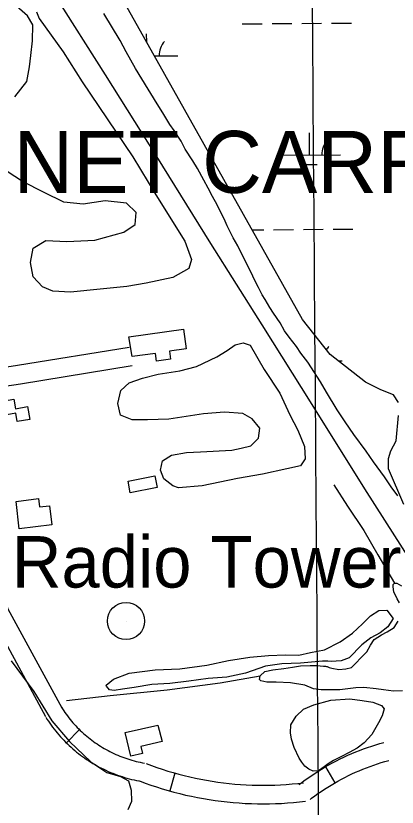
# Model space of a CAD drawing. Extents: x 3540316 to 3578335, y 553172 to 578787.
# Drawn here: x 3554547 to 3555162, y 562806 to 564084 of the extents above; entities that cross this region are included whole.
import ezdxf

# ---------------------------------------------------------------- set-up
doc = ezdxf.new("R2010")
doc.units = 0
for name, color, linetype in [('V-BLDG-OTLN', 7, 'Continuous'), ('V-GRID-MAJR', 7, 'Continuous'), ('V-RAIL-TRAK', 7, 'Continuous'), ('V-RIVR-IDEN', 7, 'Continuous'), ('V-ROAD-CNTR', 7, 'Continuous'), ('V-SITE-VEGE', 7, 'Continuous'), ('V-TOPO-SHOR', 7, 'Continuous'), ('V-TOPO-TOWR', 7, 'Continuous'), ('V-TOPO-TOWR-IDEN', 7, 'Continuous'), ('V-WETL-SWMP', 7, 'Continuous')]:
    doc.layers.add(name, color=color, linetype=linetype)

msp = doc.modelspace()

# ---------------------------------------------------------------- linework, layer by layer
at = {"layer": 'V-BLDG-OTLN'}
for points in [[(3554729.205, 563565.561), (3554817.251, 563577.914), (3554821.701, 563546.1950000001), (3554794.52, 563542.382), (3554796.345, 563529.371), (3554773.843, 563526.227), (3554772.0640000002, 563538.902), (3554734.4620000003, 563533.626)], [(3554503.2, 563457.83), (3554543.451, 563464.742), (3554546.0670000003, 563449.503), (3554565.463, 563452.833), (3554569.051, 563432.121), (3554548.9220000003, 563428.634), (3554546.538, 563442.2980000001), (3554526.035, 563438.7220000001), (3554526.764, 563434.54), (3554507.31, 563431.149)], [(3554727.659, 563332.802), (3554771.1890000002, 563341.252), (3554774.9020000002, 563322.117), (3554731.3170000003, 563313.657)], [(3554547.029, 563299.821), (3554583.363, 563304.304), (3554585.018, 563290.881), (3554600.953, 563292.8470000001), (3554604.762, 563261.969), (3554552.19, 563255.485)], [(3554782.986, 562912.378), (3554748.286, 562904.358), (3554750.883, 562893.125), (3554732.007, 562888.769), (3554723.247, 562926.689), (3554775.582, 562938.779)]]:
    msp.add_lwpolyline(points, close=True, dxfattribs=at)
at = {"layer": 'V-GRID-MAJR'}
msp.add_spline([(3555066.6580000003, 558654.5920000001), (3555020.84, 564712.414), (3554974.9990000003, 570773.3200000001), (3554929.157, 576834.2440000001), (3554929.134, 576837.311)], degree=3, dxfattribs=at)
at = {"layer": 'V-RAIL-TRAK'}
msp.add_lwpolyline([(3553552.8850000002, 565794.377), (3553643.91, 565648.182), (3553727.27, 565516.779), (3553808.107, 565388.318), (3553891.9760000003, 565255.927), (3553971.3000000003, 565128.934), (3554066.859, 564978.337), (3554158.892, 564831.1630000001), (3554249.887, 564686.956), (3554335.811, 564550.127), (3554428.325, 564403.955), (3554518.81, 564260.734), (3554609.3030000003, 564117.0160000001), (3554690.633, 563988.561), (3554773.503, 563856.653), (3554860.967, 563716.367), (3554943.8310000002, 563584.955), (3555024.168, 563456.488), (3555109.586, 563320.147), (3555202.59, 563174.479)], dxfattribs=at)
at = {"layer": 'V-ROAD-CNTR'}
for p, q in [((3554649.1916632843, 562931.471110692), (3554628.2667051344, 562909.9741536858)), ((3555046.55286856, 562871.510230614), (3555061.4498387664, 562845.4702826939)), ((3554803.11835543, 562861.2882510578), (3554795.0663715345, 562832.389308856))]:
    msp.add_line(p, q, dxfattribs=at)
for points in [[(3554374.667566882, 563496.3316520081), (3554427.0817231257, 563501.1916746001), (3554549.3744312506, 563519.5662000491), (3554729.293821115, 563549.1305035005)], [(3554379.316310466, 563466.634011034), (3554430.6982768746, 563471.3983253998), (3554554.0355687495, 563489.9297999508), (3554734.158178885, 563519.5274964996)], [(3554507.7519461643, 563196.724580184), (3554533.7138942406, 563126.6897202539), (3554620.676720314, 562966.791040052)], [(3554510.959939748, 563105.7367621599), (3554594.322773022, 562952.4570687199)], [(3554620.1637213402, 562967.6630383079), (3554621.991717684, 562964.7830440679), (3554623.914713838, 562961.89204985), (3554625.885709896, 562959.028055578), (3554627.902705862, 562956.1990612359), (3554629.949701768, 562953.4240667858), (3554632.081697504, 562950.6740722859), (3554634.2366931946, 562947.94207775), (3554636.4476887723, 562945.276083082), (3554638.7136842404, 562942.60708842), (3554640.97367972, 562940.058093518), (3554643.3426749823, 562937.4880986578), (3554645.7576701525, 562934.9351037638), (3554648.15366536, 562932.48210867), (3554650.625660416, 562930.0741134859), (3554653.1836553, 562927.6401183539), (3554655.7206502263, 562925.3091230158), (3554658.306645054, 562923.0291275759), (3554660.9466397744, 562920.7821320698), (3554663.6636343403, 562918.5441365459), (3554666.3486289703, 562916.3881408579), (3554669.086623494, 562914.304145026), (3554671.882617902, 562912.2311491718), (3554674.726612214, 562910.2111532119), (3554677.584606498, 562908.236157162), (3554680.4696007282, 562906.3391609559), (3554683.4165948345, 562904.4571647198), (3554686.347588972, 562902.6571683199), (3554689.33858299, 562900.90217183), (3554692.3755769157, 562899.1871752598), (3554695.424570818, 562897.5221785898), (3554698.4875646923, 562895.935181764), (3554701.5945584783, 562894.38218487), (3554704.72855221, 562892.9011878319), (3554707.9245458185, 562891.438190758), (3554711.081539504, 562890.0571935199), (3554714.252533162, 562888.743196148), (3554717.492526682, 562887.4841986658), (3554720.765520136, 562886.255201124), (3554724.0515135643, 562885.090203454), (3554727.335506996, 562883.9872056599), (3554730.5975004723, 562882.954207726), (3554733.9454937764, 562881.9812096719), (3554737.320487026, 562881.0382115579), (3554740.6354803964, 562880.175213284), (3554744.0314736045, 562879.374214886), (3554747.45846675, 562878.6082164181), (3554750.810460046, 562877.918217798), (3554754.320453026, 562877.2792190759)], [(3554594.835771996, 562951.585070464), (3554596.835767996, 562948.4350767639), (3554599.066763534, 562945.0800834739), (3554601.31375904, 562941.8160900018), (3554603.6147544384, 562938.5870964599), (3554606.019749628, 562935.3261029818), (3554608.4517447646, 562932.1901092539), (3554610.9107398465, 562929.0741154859), (3554613.4637347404, 562925.9941216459), (3554616.051729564, 562922.945127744), (3554618.719724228, 562919.9361337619), (3554621.416718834, 562917.0121396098), (3554624.1277134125, 562914.1451453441), (3554626.9557077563, 562911.250151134), (3554629.8197020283, 562908.4621567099), (3554632.6916962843, 562905.7281621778), (3554635.6486903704, 562903.0111676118), (3554638.6626843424, 562900.3531729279), (3554641.686678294, 562897.7801780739), (3554644.7336722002, 562895.2701830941), (3554647.86866593, 562892.7521881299), (3554651.066659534, 562890.318192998), (3554654.260653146, 562887.949197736), (3554657.514646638, 562885.6392023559), (3554660.8126400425, 562883.360206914), (3554664.15363336, 562881.1632113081), (3554667.4906266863, 562879.0312155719), (3554670.907619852, 562876.9332197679), (3554674.370612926, 562874.90222383), (3554677.8096060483, 562872.959227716), (3554681.336598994, 562871.034231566), (3554684.879591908, 562869.1992352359), (3554688.476584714, 562867.400238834), (3554692.0765775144, 562865.6992422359), (3554695.670570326, 562864.0542455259), (3554699.327563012, 562862.455248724), (3554703.0765555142, 562860.901251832), (3554706.786548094, 562859.460254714), (3554710.4775407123, 562858.0732574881), (3554714.261533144, 562856.73226017), (3554718.0295256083, 562855.465262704), (3554721.8815179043, 562854.246265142), (3554725.7215102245, 562853.1292673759), (3554729.506502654, 562852.07226949), (3554733.415494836, 562851.055271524), (3554737.315487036, 562850.136273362), (3554741.156479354, 562849.2762750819), (3554745.096471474, 562848.464276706), (3554748.94846377, 562847.7632781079)], [(3555003.3649549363, 562842.578288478), (3555005.7949500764, 562844.44228475), (3555011.2839390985, 562848.5382765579), (3555016.894927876, 562852.553268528), (3555022.5049166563, 562856.431260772), (3555028.2459051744, 562860.2772530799), (3555034.026893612, 562863.9702456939), (3555039.904881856, 562867.6082384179), (3555045.813870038, 562871.0872314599), (3555051.7458581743, 562874.4812246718), (3555057.7558461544, 562877.78721806), (3555063.90783385, 562881.0172115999), (3555070.0468215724, 562884.068205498), (3555076.1848092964, 562887.033199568), (3555082.461796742, 562889.9191937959), (3555088.724784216, 562892.678188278), (3555095.106771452, 562895.3551829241), (3555101.518758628, 562897.868177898), (3555107.8737459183, 562900.28217307), (3555114.384732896, 562902.6231683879), (3555120.92771981, 562904.806164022), (3555127.4127068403, 562906.890159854), (3555134.013693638, 562908.8861558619), (3555140.5676805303, 562910.704152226)], [(3554756.8754479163, 562876.575220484), (3554765.3904308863, 562873.4002268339), (3554774.069413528, 562870.3202329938), (3554782.8583959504, 562867.4022388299), (3554791.666378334, 562864.6022444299), (3554800.49836067, 562862.018249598), (3554809.40834285, 562859.5362545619), (3554818.299325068, 562857.231259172), (3554827.28830709, 562855.093263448), (3554836.299289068, 562853.1042674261), (3554845.362270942, 562851.241271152), (3554854.3992528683, 562849.5872744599), (3554863.5282346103, 562848.05227753), (3554872.6432163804, 562846.724280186), (3554881.8381979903, 562845.5032826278), (3554890.962179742, 562844.445284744), (3554900.130161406, 562843.56228651), (3554909.332143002, 562842.883287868), (3554918.5461245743, 562842.3082890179), (3554927.8141060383, 562841.9042898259), (3554937.01308764, 562841.6522903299), (3554946.1920692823, 562841.565290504), (3554955.451050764, 562841.6922902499), (3554964.6850322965, 562841.9212897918), (3554973.86301394, 562842.3092890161), (3554983.1149954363, 562842.916287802), (3554992.3449769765, 562843.626286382), (3555001.4679587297, 562844.485284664), (3555010.745940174, 562845.5752824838)], [(3555021.6269184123, 562818.776336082), (3555023.8969138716, 562820.518332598), (3555028.983903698, 562824.314325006), (3555034.1548933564, 562828.0133176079), (3555039.3848828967, 562831.6293103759), (3555044.671872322, 562835.1713032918), (3555049.9968616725, 562838.5742964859), (3555055.4108508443, 562841.9242897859), (3555060.873839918, 562845.1412833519), (3555066.425828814, 562848.3172769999), (3555071.959817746, 562851.361270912), (3555077.55780655, 562854.3012650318), (3555083.246795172, 562857.128259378), (3555088.9767837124, 562859.895253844), (3555094.775772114, 562862.563248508), (3555100.57276052, 562865.116243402), (3555106.384748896, 562867.5532385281), (3555112.318737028, 562869.8802338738), (3555118.275725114, 562872.1422293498), (3555124.2087132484, 562874.2752250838), (3555130.263701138, 562876.2962210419), (3555136.34268898, 562878.2482171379), (3555142.3656769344, 562880.0702134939), (3555148.5876644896, 562881.796210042)], [(3554746.39346888, 562848.4672767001), (3554755.130451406, 562845.208283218), (3554764.325433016, 562841.9442897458), (3554773.586414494, 562838.8702958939), (3554782.90839585, 562835.9063018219), (3554792.262377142, 562833.1703072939), (3554801.61835843, 562830.564312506), (3554811.0633395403, 562828.115317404), (3554820.584320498, 562825.8513219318), (3554830.045301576, 562823.7623261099), (3554839.642282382, 562821.7893300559), (3554849.211263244, 562820.039333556), (3554858.8782439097, 562818.4123368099), (3554868.5072246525, 562817.0103396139), (3554878.136205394, 562815.7313421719), (3554887.796186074, 562814.6113444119), (3554897.58816649, 562813.668346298), (3554907.294147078, 562812.9513477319), (3554916.960127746, 562812.348348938), (3554926.7501081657, 562811.9223497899), (3554936.459088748, 562811.6563503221), (3554946.256069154, 562811.563350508), (3554956.0290496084, 562811.6983502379), (3554965.691030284, 562811.9373497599), (3554975.4790107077, 562812.351348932), (3554985.246991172, 562812.9923476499), (3554994.900971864, 562813.7343461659), (3555004.6239524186, 562814.649344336), (3555014.245933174, 562815.7793420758)]]:
    msp.add_lwpolyline(points, dxfattribs=at)
at = {"layer": 'V-SITE-VEGE'}
for points in [[(3554544.811, 563952.893), (3554564.523, 563977.643), (3554568.568, 564001.535), (3554570.813, 564019.758), (3554573.602, 564043.634), (3554573.858, 564069.355), (3554565.4960000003, 564083.66), (3554548.338, 564099.091)], [(3554579.828, 564090.14), (3554584.373, 564079.5430000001), (3554622.791, 564025.529), (3554653.603, 563977.051), (3554735.646, 563855.928), (3554772.2830000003, 563794.988), (3554819.161, 563719.7710000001), (3554830.2490000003, 563690.452), (3554826.069, 563675.964), (3554799.9390000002, 563661.159), (3554756.785, 563652.38), (3554725.504, 563646.909), (3554682.916, 563642.529), (3554634.69, 563637.437), (3554606.434, 563639.537), (3554589.4020000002, 563646.191), (3554574.7430000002, 563662.286), (3554570.0160000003, 563685.422), (3554574.698, 563708.702), (3554595.219, 563720.916), (3554629.109, 563719.525), (3554674.2430000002, 563721.434), (3554721.095, 563734.656), (3554739.109, 563746.838), (3554740.7090000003, 563766.306), (3554725.441, 563781.137), (3554690.8850000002, 563785.029), (3554655.213, 563779.493), (3554623.801, 563782.8), (3554592.208, 563798.654), (3554557.454, 563816.334), (3554532.761, 563832.2880000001)], [(3555163.2770000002, 563309.049), (3555152.344, 563323.481), (3555141.424, 563339.572), (3555123.943, 563363.995), (3555111.927, 563381.198), (3555092.254, 563407.8420000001), (3555078.055, 563428.3740000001), (3555064.952, 563447.7930000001), (3555048.052, 563476.073), (3555038.238, 563492.707), (3555018.057, 563524.877), (3555006.572, 563539.316), (3554999.473, 563549.857), (3554987.994, 563564.848), (3554980.347, 563575.393), (3554973.2630000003, 563588.144), (3554962.339, 563603.682), (3554956.338, 563613.111), (3554949.259, 563625.862), (3554944.347, 563633.6240000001), (3554938.363, 563645.265), (3554931.285, 563658.567), (3554929.112, 563663.551), (3554920.9590000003, 563680.1730000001), (3554914.426, 563692.367), (3554904.6410000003, 563712.314), (3554897.565, 563725.6140000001), (3554887.771, 563745.011), (3554884.5130000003, 563752.211), (3554871.465, 563778.807), (3554863.8340000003, 563792.113), (3554856.761, 563805.414), (3554850.236, 563818.71), (3554839.887, 563837.558), (3554832.25, 563849.76), (3554819.696, 563868.6240000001), (3554813.167, 563881.3690000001), (3554802.255, 563898.564), (3554795.1550000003, 563908.554), (3554783.702, 563927.408), (3554774.427, 563941.832), (3554749.89, 563982.312), (3554739.5270000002, 563998.952), (3554724.8200000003, 564025.558), (3554715.021, 564043.851), (3554688.853, 564087.657)], [(3554539.1920000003, 563042.68), (3554557.114, 563017.85), (3554575.664, 562993.028), (3554604.574, 562945.777), (3554633.287, 562912.323), (3554667.632, 562879.5750000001), (3554693.598, 562862.39), (3554715.647, 562855.81), (3554728.3000000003, 562848.466), (3554732.9080000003, 562833.481), (3554733.17, 562815.292), (3554727.089, 562802.034)]]:
    msp.add_lwpolyline(points, dxfattribs=at)
for points in [[(3554924.826, 563552.2980000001), (3554947.548, 563512.88), (3554972.862, 563474.81), (3554989.002, 563439.861), (3555001.7490000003, 563414.636), (3555012.548, 563388.73), (3555013.492, 563368.545), (3555005.8370000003, 563357.357), (3554983.753, 563352.479), (3554944.784, 563344.094), (3554904.491, 563336.9940000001), (3554847.328, 563325.089), (3554808.934, 563321.927), (3554799.767, 563325.052), (3554785.265, 563336.5700000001), (3554779.856, 563350.1730000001), (3554783.5470000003, 563365.209), (3554797.745, 563374.54), (3554821.791, 563378.7980000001), (3554844.579, 563379.779), (3554895.361, 563382.47), (3554910.295, 563385.943), (3554925.883, 563389.429), (3554938.0810000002, 563401.983), (3554940.45, 563418.308), (3554927.857, 563433.111), (3554912.741, 563442.011), (3554883.3910000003, 563444.192), (3554849.556, 563441.096), (3554793.647, 563432.4670000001), (3554759.132, 563431.314), (3554734.37, 563431.607), (3554715.367, 563439.15), (3554711.187, 563457.983), (3554716.094, 563478.906), (3554729.592, 563491.481), (3554750.986, 563498.958), (3554776.305, 563505.1900000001), (3554811.406, 563510.91), (3554838.017, 563517.812), (3554871.025, 563533.274), (3554887.819, 563543.291), (3554900.713, 563552.599), (3554913.6950000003, 563556.046)], [(3555041.685, 563041.881), (3555005.894, 563038.756), (3554975.94, 563037.67), (3554949.279, 563034.027), (3554917.521, 563022.4890000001), (3554886.989, 563016.183), (3554857.0530000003, 563013.795), (3554825.842, 563009.433), (3554795.274, 563005.732), (3554765.9790000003, 563004.003), (3554737.3740000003, 562999.68), (3554718.519, 562996.801), (3554705.522, 562994.656), (3554697.684, 562995.846), (3554693.039, 563001.642), (3554692.37, 563002.936), (3554703.953, 563012.877), (3554729.228, 563022.366), (3554771.492, 563028.1900000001), (3554811.217, 563029.419), (3554854.786, 563035.262), (3554889.858, 563042.938), (3554924.308, 563048.65), (3554954.2430000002, 563051.0380000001), (3554981.594, 563052.086), (3555003.1, 563051.746), (3555021.934, 563055.928), (3555044.677, 563060.1680000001), (3555069.9020000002, 563072.912), (3555089.897, 563086.886), (3555105.965, 563102.105), (3555118.804, 563115.3200000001), (3555132.362, 563123.987), (3555145.389, 563124.176), (3555155.359, 563110.639), (3555147.079, 563097.486), (3555134.844, 563087.537), (3555119.324, 563079.493), (3555105.1520000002, 563068.212), (3555084.611, 563047.0650000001), (3555071.647, 563042.3150000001), (3555055.376, 563041.428), (3555050.151, 563042.004)]]:
    msp.add_lwpolyline(points, close=True, dxfattribs=at)
at = {"layer": 'V-TOPO-SHOR'}
for points in [[(3555059.916, 563326.838), (3555081.965, 563292.384), (3555108.001, 563253.091), (3555131.1, 563213.755), (3555157.757, 563168.13)], [(3554628.542, 562978.235), (3554698.9560000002, 562986.606), (3554790.913, 562995.777), (3554876.477, 563006.813), (3554940.974, 563018.034)], [(3555004.131, 562885.223), (3554996.039, 562902.74), (3554991.4390000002, 562915.898), (3554989.821, 562926.1630000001), (3554990.61, 562939.399), (3554999.2260000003, 562953.24), (3555010.815, 562964.676), (3555027.373, 562971.282), (3555055.183, 562979.034), (3555085.526, 562980.943), (3555105.648, 562978.297), (3555122.8310000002, 562975.606), (3555136.622, 562970.4180000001), (3555141.107, 562965.093), (3555137.842, 562953.78), (3555132.129, 562942.43), (3555121.1350000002, 562923.658), (3555108.595, 562910.25), (3555097.458, 562901.272), (3555084.3340000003, 562894.224), (3555072.1750000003, 562888.1680000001), (3555059.535, 562881.6190000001), (3555050.796, 562876.104), (3555044.011, 562871.107), (3555035.2830000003, 562865.102), (3555026.474, 562864.483), (3555019.575, 562867.324), (3555013.13, 562872.618), (3555008.1410000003, 562878.914), (3555004.131, 562885.223)]]:
    msp.add_lwpolyline(points, dxfattribs=at)
at = {"layer": 'V-TOPO-TOWR'}
msp.add_line((3554724.5044610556, 563106.7310304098), (3554724.5044610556, 563106.7310304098), dxfattribs=at)
msp.add_circle((3554724.5044610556, 563106.7310304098), 29.999940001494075, dxfattribs=at)
at = {"layer": 'V-WETL-SWMP'}
for p, q in [((3555008.1163868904, 564071.6053277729), (3555040.115426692, 564071.8520039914)), ((3555056.1149465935, 564071.9753421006), (3555088.1139863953, 564072.2220183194)), ((3554912.1192674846, 564070.865299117), (3554944.1183072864, 564071.1119753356)), ((3554960.1178271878, 564071.2353134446), (3554992.116866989, 564071.4819896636)), ((3554757.7460835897, 564041.900454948), (3554757.6455875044, 564054.9321433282)), ((3554770.5808759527, 564019.0310310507), (3554807.9216972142, 564019.3188863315)), ((3555020.5995337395, 563859.0926649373), (3555020.3219237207, 563895.0913535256)), ((3554970.601034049, 563858.7072333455), (3555070.59803343, 563859.4780965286)), ((3555008.7188882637, 563843.5697234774), (3555032.7181681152, 563843.7547306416)), ((3555058.6803330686, 563739.3124608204), (3555090.6793728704, 563739.5591370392)), ((3554928.129518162, 563738.3060624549), (3554946.683693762, 563738.4490940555)), ((3554962.683213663, 563738.5724321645), (3554994.6822534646, 563738.8191083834)), ((3555010.6817733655, 563738.9424464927), (3555042.6808131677, 563739.1891227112)), ((3555066.8307313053, 563526.7663974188), (3555073.1634199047, 563526.8152152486))]:
    msp.add_line(p, q, dxfattribs=at)
for points in [[(3555164.369, 563459.365), (3555156.153, 563471.689), (3555135.613, 563479.905), (3555110.965, 563492.229), (3555053.978, 563536.809), (3555009.21, 563593.8200000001), (3554628.6, 564272.008), (3554529.9450000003, 564446.31), (3554515.657, 564484.545), (3554518.041, 564509.2930000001), (3554526.077, 564523.14), (3554555.9960000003, 564542.799), (3554632.465, 564571.376), (3554758.312, 564603.419), (3554835.103, 564610.033), (3554920.21, 564611.276), (3555027.44, 564601.858)], [(3555172.586, 563295.042), (3555147.937, 563352.555), (3555147.937, 563368.987), (3555152.045, 563381.311), (3555160.261, 563397.7440000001), (3555164.369, 563438.824)], [(3555165.573, 563135.914), (3555162.045, 563142.721), (3555156.495, 563153.907), (3555155.401, 563161.729), (3555155.8340000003, 563165.654), (3555157.758, 563168.131), (3555161.683, 563167.698), (3555169.093, 563163.397)], [(3555170.5700000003, 562993.932), (3555156.375, 562993.236), (3555140.1780000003, 562995.451), (3555127.906, 562997.232), (3555108.281, 562999.397), (3555095.555, 562998.723), (3555069.634, 562995.898), (3555053.9620000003, 562995.67), (3555039.27, 562995.457), (3555026.998, 562997.2390000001), (3555013.2, 563002.917), (3554989.629, 563006.984), (3554966.59, 563008.1190000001), (3554951.897, 563007.906), (3554942.0670000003, 563010.213), (3554940.08, 563012.143), (3554940.974, 563018.035), (3554948.221, 563024.997), (3554961.401, 563028.128), (3554979.0100000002, 563029.852), (3554993.185, 563032.017), (3555005.889, 563034.161), (3555021.554, 563034.878), (3555032.328, 563035.034), (3555043.1240000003, 563033.721), (3555046.552, 563033.7710000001), (3555047.775, 563033.354), (3555049.268, 563033.1460000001), (3555052.495, 563031.931), (3555056.411, 563030.612), (3555067.6890000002, 563028.689), (3555079.436, 563029.349), (3555088.216, 563031.926), (3555094.987, 563037.902), (3555104.15, 563047.832), (3555112.8370000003, 563056.775), (3555119.048, 563067.6410000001), (3555124.79, 563077.032), (3555136.927, 563084.555), (3555145.6780000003, 563089.091), (3555157.332, 563096.118), (3555163.5500000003, 563106.4940000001)]]:
    msp.add_lwpolyline(points, dxfattribs=at)
for centre, radius, start, end in [((3554813.160814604, 564019.8340880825), 35.246287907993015, 139.66984859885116, 181.2135069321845), ((3554965.3545938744, 563859.1416033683), 35.24628790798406, 359.6698614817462, 41.21351981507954), ((3555075.8371508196, 563859.9932982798), 35.246287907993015, 139.66984859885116, 181.2135069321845), ((3555078.4025372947, 563527.3304169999), 35.246287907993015, 139.66984859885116, 150.3939908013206)]:
    msp.add_arc(centre, radius, start, end, dxfattribs=at)

# ---------------------------------------------------------------- texts
at = {"layer": 'V-RIVR-IDEN'}
msp.add_text('BONNET CARRE CREVASSE 1874', height=99.99980199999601, dxfattribs=at).set_placement((3554252.8944558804, 563797.977377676))
at = {"layer": 'V-TOPO-TOWR-IDEN'}
msp.add_text('Radio Tower', height=82.99983200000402, dxfattribs=at).set_placement((3554540.070881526, 563160.7766520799))

doc.saveas('drawing.dxf')
